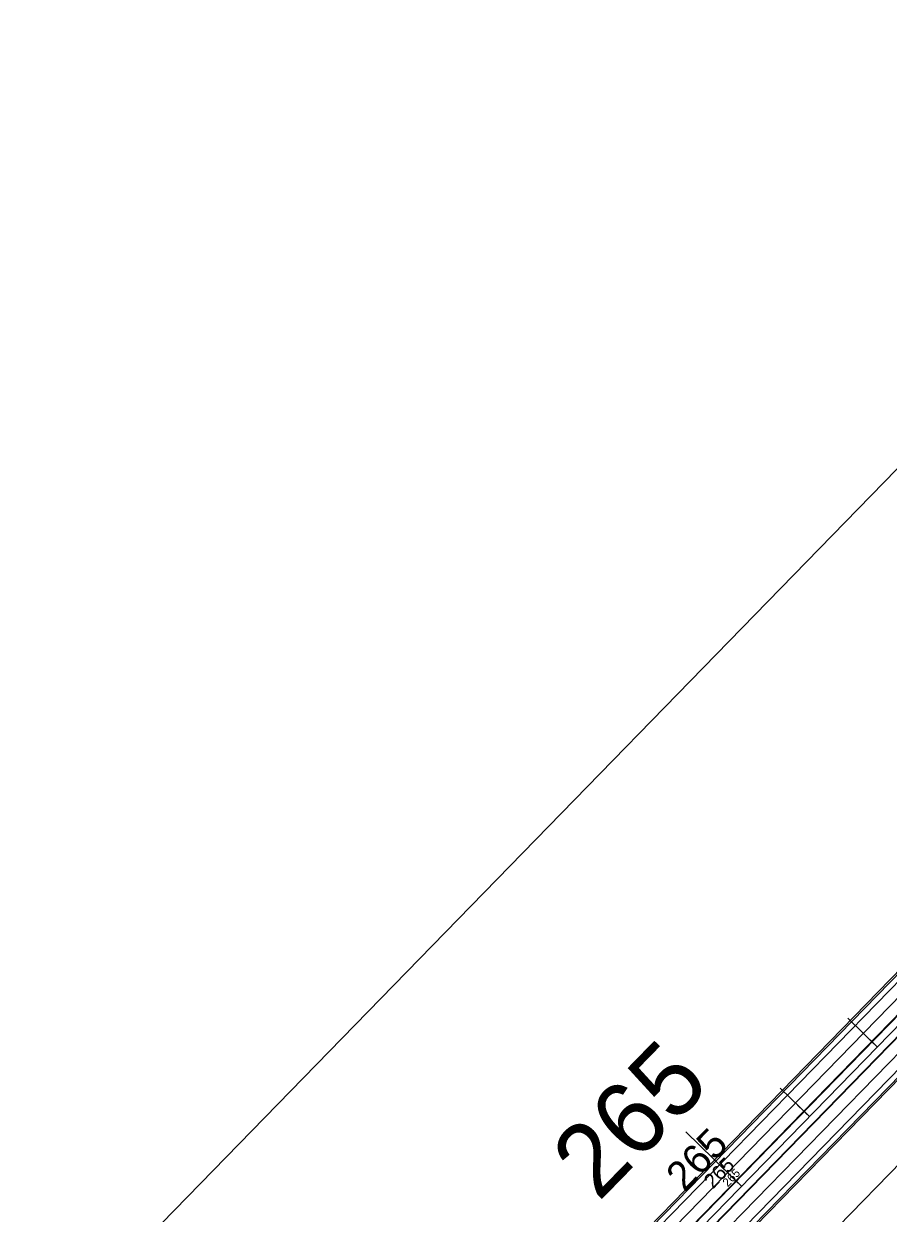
# Model space of a CAD drawing. Extents: x 2358865 to 2362945, y 393485 to 404880.
# Drawn here: x 2359689 to 2360577, y 398777 to 399999 of the extents above; entities that cross this region are included whole.
import ezdxf

# ---------------------------------------------------------------- set-up
doc = ezdxf.new("R2010")
doc.units = 0
for name, color, linetype in [('CL', 7, 'Continuous'), ('Level 19', 7, 'Continuous'), ('Level 25', 7, 'Continuous'), ('Level 27', 7, 'Continuous'), ('Level 30', 7, 'Continuous'), ('Level 35', 7, 'Continuous'), ('Level 37', 7, 'Continuous'), ('Level 39', 7, 'Continuous'), ('Level 41', 7, 'Continuous'), ('Level 48', 7, 'Continuous'), ('Level 58', 7, 'Continuous'), ('Level 63', 7, 'Continuous'), ('STAEQU', 7, 'Continuous')]:
    doc.layers.add(name, color=color, linetype=linetype)

msp = doc.modelspace()

# ---------------------------------------------------------------- linework, layer by layer
at = {"layer": 'CL'}
msp.add_line((2359688.9, 398047.8), (2361589.9, 399999.4), dxfattribs=at)
at = {"layer": 'Level 19'}
for p, q in [((2359821.6, 398212.7), (2361205.3, 399633.2)), ((2359850.3, 398184.8), (2361234, 399605.3))]:
    msp.add_line(p, q, dxfattribs=at)
at = {"layer": 'Level 25'}
for p, q in [((2360565.7, 398948), (2360562.2, 398951.5)), ((2360496, 398876.3), (2360492.4, 398879.8)), ((2360426.2, 398804.7), (2360420.5, 398810.3))]:
    msp.add_line(p, q, dxfattribs=at)
at = {"layer": 'Level 27'}
msp.add_line((2359817.5, 398036.5), (2361439.8, 399702), dxfattribs=at)
at = {"layer": 'Level 30'}
for p, q in [((2360565.7, 398948), (2360559.6, 398953.9)), ((2360496, 398876.3), (2360489.9, 398882.3)), ((2360426.2, 398804.7), (2360414.7, 398815.9))]:
    msp.add_line(p, q, dxfattribs=at)
at = {"layer": 'Level 35'}
for p, q in [((2359821.6, 398212.7), (2361205.3, 399633.2)), ((2359850.3, 398184.8), (2361234, 399605.3))]:
    msp.add_line(p, q, dxfattribs=at)
at = {"layer": 'Level 37'}
for p, q in [((2359830.2, 398204.4), (2361213.9, 399624.9)), ((2359830.6, 398204), (2361214.3, 399624.5)), ((2359841.3, 398193.6), (2361225, 399614)), ((2359841.7, 398193.2), (2361225.4, 399613.7))]:
    msp.add_line(p, q, dxfattribs=at)
at = {"layer": 'Level 39'}
for p, q in [((2360565.7, 398948), (2360553.6, 398959.8)), ((2360496, 398876.3), (2360483.8, 398888.2)), ((2360426.2, 398804.7), (2360403.3, 398827))]:
    msp.add_line(p, q, dxfattribs=at)
at = {"layer": 'Level 41'}
for p, q in [((2360565.7, 398948), (2360535.6, 398977.3)), ((2360496, 398876.3), (2360465.9, 398905.6)), ((2360426.2, 398804.7), (2360368.9, 398860.5))]:
    msp.add_line(p, q, dxfattribs=at)
at = {"layer": 'Level 48'}
for p, q in [((2361214.3, 399624.5), (2359830.6, 398204)), ((2359841.3, 398193.6), (2361225, 399614))]:
    msp.add_line(p, q, dxfattribs=at)
at = {"layer": 'Level 58'}
for p, q in [((2359947.9, 398369), (2361129.8, 399582.4)), ((2360003.2, 398315.1), (2361185.1, 399528.5))]:
    msp.add_line(p, q, dxfattribs=at)
at = {"layer": 'Level 63'}
msp.add_lwpolyline([(2360837.4, 399800.1), (2359790.8, 398725.6), (2360363.8, 398167.4), (2360363.8, 398167.4), (2361410.5, 399241.9), (2361410.5, 399241.9)], close=True, dxfattribs=at)
at = {"layer": 'STAEQU'}
for p, q in [((2359949, 398367.9), (2361193.1, 399645.1)), ((2361197.1, 399641.3), (2359953, 398364)), ((2359998.1, 398320.1), (2361242.2, 399597.3)), ((2361246.1, 399593.5), (2360002, 398316.2))]:
    msp.add_line(p, q, dxfattribs=at)

# ---------------------------------------------------------------- texts
at = {"layer": 'Level 25'}
msp.add_text('265', height=8.75, rotation=45.7519, dxfattribs=at).set_placement((2360412.1, 398803.5))
at = {"layer": 'Level 30'}
msp.add_text('265', height=15, rotation=45.7519, dxfattribs=at).set_placement((2360396.9, 398801.4))
at = {"layer": 'Level 39'}
msp.add_text('265', height=30, rotation=45.7519, dxfattribs=at).set_placement((2360367.6, 398798.1))
at = {"layer": 'Level 41'}
msp.add_text('265', height=75, rotation=45.7519, dxfattribs=at).set_placement((2360279.4, 398788))

doc.saveas('drawing.dxf')
